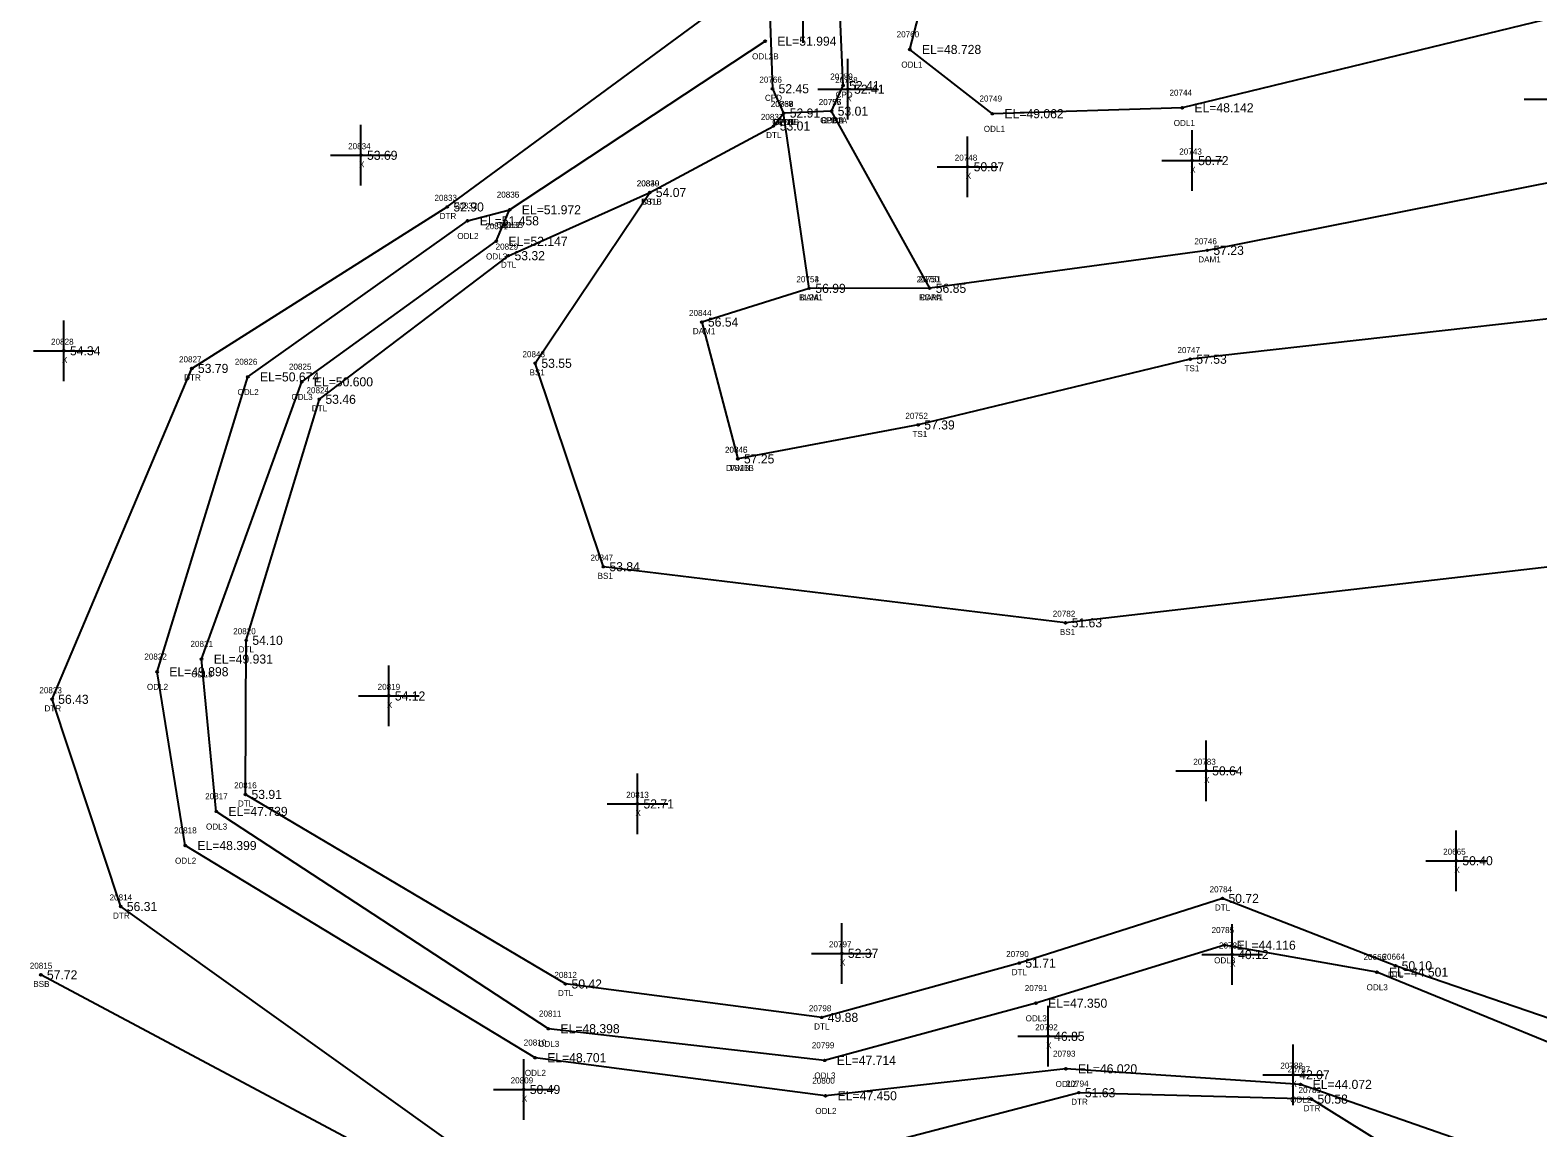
# Model space of a CAD drawing. Extents: x 2420351 to 2422725, y 845330 to 846558.
# Drawn here: x 2421386.7 to 2421635.3, y 845844 to 846025.1 of the extents above; entities that cross this region are included whole.
import ezdxf

# ---------------------------------------------------------------- set-up
doc = ezdxf.new("R2010")
doc.units = 0
for name, color, linetype in [('RD_DTM_BkLn1', 7, 'Continuous'), ('RD_DTM_BkLn2', 7, 'Continuous'), ('RD_DTM_BkLn_txCode', 7, 'Continuous'), ('RD_EX_Conc', 7, 'Continuous'), ('RD_EX_Conc_txCode', 7, 'Continuous'), ('RD_EX_Dam', 7, 'Continuous'), ('RD_EX_Dam_txCode', 7, 'Continuous'), ('RD_EX_DR_ErosCtrl', 7, 'Continuous'), ('RD_EX_DR_ErosCtrl_txCode', 7, 'Continuous'), ('RD_EX_H2O', 7, 'Continuous'), ('RD_EX_H2O_txCode', 7, 'Continuous'), ('RD_EX_Misc', 7, 'Continuous'), ('RD_EX_Misc_txCode', 7, 'Continuous'), ('RD_EX_TX_Conc_ELEV', 7, 'Continuous'), ('RD_EX_TX_Dam_ELEV', 7, 'Continuous'), ('RD_EX_TX_DR_ErosCtrl_ELEV', 7, 'Continuous'), ('RD_EX_TX_H2O_ELEV', 7, 'Continuous'), ('RD_EX_TX_Misc_ELEV', 7, 'Continuous'), ('RD_SMD_Locator', 7, 'Continuous')]:
    doc.layers.add(name, color=color, linetype=linetype)

msp = doc.modelspace()

# ---------------------------------------------------------------- linework, layer by layer
at = {"layer": 'RD_DTM_BkLn1'}
msp.add_line((2421515.21, 845982.5), (2421510.99, 846011.42), dxfattribs=at)
at = {"layer": 'RD_DTM_BkLn2'}
for points in [[(2421645.39, 845937.48), (2421557.48, 845927.33), (2421481.26, 845936.58), (2421470.04, 845970.14), (2421488.91, 845998.31)], [(2421645.39, 845937.48), (2421642.53, 845978.05), (2421578.04, 845970.81), (2421533.18, 845959.97), (2421503.44, 845954.37)], [(2421481.47, 845840.1), (2421460.78, 845830.74), (2421388.51, 845869.26)]]:
    msp.add_lwpolyline(points, dxfattribs=at)
at = {"layer": 'RD_EX_Conc'}
msp.add_line((2421518.9, 846011.73), (2421510.99, 846011.42), dxfattribs=at)
msp.add_lwpolyline([(2421518.9, 846011.73), (2421520.79, 846015.94), (2421519.59, 846043.78), (2421517.87, 846047.43), (2421509.82, 846047.43), (2421508.14, 846043.13), (2421509.15, 846015.43), (2421510.99, 846011.42)], dxfattribs=at)
at = {"layer": 'RD_EX_Dam'}
msp.add_lwpolyline([(2421642.53, 845978.05), (2421639.05, 846000.31), (2421580.85, 845988.77), (2421535.07, 845982.51), (2421515.21, 845982.5), (2421497.5, 845976.94), (2421503.44, 845954.37)], dxfattribs=at)
at = {"layer": 'RD_EX_DR_ErosCtrl'}
msp.add_line((2421535.07, 845982.51), (2421518.9, 846011.73), dxfattribs=at)
at = {"layer": 'RD_EX_H2O'}
for points in [[(2421769.97, 845784.59), (2421757.53, 845787.6), (2421742.96, 845811.73), (2421745.62, 845824.92), (2421731.55, 845840.59), (2421714.37, 845860.98), (2421703.55, 845865.16), (2421670.27, 845895.91), (2421653.18, 845938.84), (2421661.84, 845966.62), (2421645.65, 846012.9), (2421638.29, 846027.24), (2421576.72, 846012.28), (2421545.4, 846011.31), (2421531.8, 846021.91), (2421540.87, 846056.88), (2421568.83, 846092.43), (2421605.18, 846118.43)], [(2421712.23, 845851.64), (2421696.17, 845853.46), (2421673.72, 845844.59), (2421672.85, 845833.86), (2421657.19, 845821.05), (2421639.52, 845822.79), (2421628.75, 845828.72), (2421620.88, 845834.5), (2421598.01, 845848.76), (2421559.66, 845849.82), (2421519.66, 845839.33), (2421490.26, 845831.77), (2421489.16, 845834.56), (2421488.34, 845838.76), (2421481.47, 845840.1), (2421478.52, 845840.67), (2421462.88, 845836.78), (2421401.68, 845880.53), (2421390.37, 845914.71), (2421413.41, 845969.29), (2421455.53, 845995.93), (2421500.71, 846029.14), (2421506.65, 846045.11), (2421509.82, 846047.43)], [(2421708.19, 845857.7), (2421694.83, 845854.97), (2421672.77, 845845.6), (2421652.18, 845835.21), (2421629.45, 845839.56), (2421596.22, 845851.19), (2421557.52, 845853.76), (2421517.9, 845849.31), (2421470, 845855.59), (2421412.32, 845890.59), (2421407.69, 845919.26), (2421422.64, 845967.89), (2421458.88, 845993.64), (2421465.81, 845995.46), (2421507.94, 846023.27)], [(2421697.78, 845867.71), (2421684.61, 845864.63), (2421657.29, 845855.17), (2421611.89, 845870.76), (2421583.33, 845881.87), (2421549.84, 845871.2), (2421517.26, 845862.24), (2421475.01, 845867.75), (2421422.24, 845899.02), (2421422.38, 845924.44), (2421434.43, 845964.2), (2421465.61, 845987.89), (2421488.91, 845998.31), (2421509.34, 846009.28), (2421510.99, 846011.42)], [(2421703.55, 845865.16), (2421687.39, 845862.16), (2421656.9, 845850), (2421608.8, 845869.71), (2421583.67, 845874.15), (2421552.59, 845864.58), (2421517.75, 845855.15), (2421472.19, 845860.37), (2421417.44, 845896.22), (2421415.01, 845921.35), (2421431.52, 845967.08), (2421463.61, 845990.26), (2421465.81, 845995.46)]]:
    msp.add_lwpolyline(points, dxfattribs=at)
at = {"layer": 'RD_EX_Misc'}
for p, q in [((2421514.19, 846023.01), (2421514.19, 846033.01)), ((2421521.6, 846010.35), (2421521.6, 846020.35)), ((2421516.6, 846015.35), (2421526.6, 846015.35)), ((2421633.08, 846013.68), (2421643.08, 846013.68)), ((2421441.29, 845999.45), (2421441.29, 846009.45)), ((2421541.32, 845997.56), (2421541.32, 846007.56)), ((2421578.33, 845998.57), (2421578.33, 846008.57)), ((2421436.29, 846004.45), (2421446.29, 846004.45)), ((2421536.32, 846002.56), (2421546.32, 846002.56)), ((2421573.33, 846003.57), (2421583.33, 846003.57)), ((2421392.31, 845967.2), (2421392.31, 845977.2)), ((2421387.31, 845972.2), (2421397.31, 845972.2)), ((2421445.88, 845910.26), (2421445.88, 845920.26)), ((2421440.88, 845915.26), (2421450.88, 845915.26)), ((2421580.65, 845897.91), (2421580.65, 845907.91)), ((2421486.87, 845892.45), (2421486.87, 845902.45)), ((2421575.65, 845902.91), (2421585.65, 845902.91)), ((2421481.87, 845897.45), (2421491.87, 845897.45)), ((2421621.9, 845883.08), (2421621.9, 845893.08)), ((2421616.9, 845888.08), (2421626.9, 845888.08)), ((2421520.58, 845867.8), (2421520.58, 845877.8)), ((2421584.93, 845867.6), (2421584.93, 845877.6)), ((2421515.58, 845872.8), (2421525.58, 845872.8)), ((2421579.93, 845872.6), (2421589.93, 845872.6)), ((2421554.59, 845854.12), (2421554.59, 845864.12)), ((2421549.59, 845859.12), (2421559.59, 845859.12)), ((2421595.01, 845847.78), (2421595.01, 845857.78)), ((2421468.13, 845845.35), (2421468.13, 845855.35)), ((2421590.01, 845852.78), (2421600.01, 845852.78)), ((2421463.13, 845850.35), (2421473.13, 845850.35))]:
    msp.add_line(p, q, dxfattribs=at)
at = {"layer": 'RD_SMD_Locator'}
for centre in [(2421507.94, 846023.27), (2421531.8, 846021.91), (2421509.15, 846015.43), (2421520.79, 846015.94), (2421521.6, 846015.35), (2421510.99, 846011.42), (2421510.99, 846011.42), (2421510.99, 846011.42), (2421510.99, 846011.42), (2421518.9, 846011.73), (2421518.9, 846011.73), (2421518.9, 846011.73), (2421545.4, 846011.31), (2421576.72, 846012.28), (2421509.34, 846009.28), (2421441.29, 846004.45), (2421541.32, 846002.56), (2421578.33, 846003.57), (2421488.91, 845998.31), (2421488.91, 845998.31), (2421455.53, 845995.93), (2421465.81, 845995.46), (2421465.81, 845995.46), (2421458.88, 845993.64), (2421463.61, 845990.26), (2421465.61, 845987.89), (2421580.85, 845988.77), (2421515.21, 845982.5), (2421515.21, 845982.5), (2421535.07, 845982.51), (2421535.07, 845982.51), (2421497.5, 845976.94), (2421392.31, 845972.2), (2421413.41, 845969.29), (2421470.04, 845970.14), (2421578.04, 845970.81), (2421422.64, 845967.89), (2421431.52, 845967.08), (2421434.43, 845964.2), (2421533.18, 845959.97), (2421503.44, 845954.37), (2421503.44, 845954.37), (2421481.26, 845936.58), (2421557.48, 845927.33), (2421422.38, 845924.44), (2421407.69, 845919.26), (2421415.01, 845921.35), (2421390.37, 845914.71), (2421445.88, 845915.26), (2421580.65, 845902.91), (2421422.24, 845899.02), (2421486.87, 845897.45), (2421417.44, 845896.22), (2421412.32, 845890.59), (2421621.9, 845888.08), (2421401.68, 845880.53), (2421583.33, 845881.87), (2421520.58, 845872.8), (2421583.67, 845874.15), (2421584.93, 845872.6), (2421549.84, 845871.2), (2421608.8, 845869.71), (2421611.89, 845870.76), (2421388.51, 845869.26), (2421475.01, 845867.75), (2421552.59, 845864.58), (2421517.26, 845862.24), (2421472.19, 845860.37), (2421554.59, 845859.12), (2421470, 845855.59), (2421517.75, 845855.15), (2421557.52, 845853.76), (2421595.01, 845852.78), (2421468.13, 845850.35), (2421559.66, 845849.82), (2421596.22, 845851.19), (2421517.9, 845849.31), (2421598.01, 845848.76)]:
    msp.add_circle(centre, 0.15, dxfattribs=at)

# ---------------------------------------------------------------- texts
at = {"layer": 'RD_DTM_BkLn_txCode'}
for s, p in [('20769', (2421508.85, 846012.42)), ('BL2B', (2421509.32, 846009.42)), ('20849', (2421486.79, 845999.31)), ('BS1B', (2421487.49, 845996.31)), ('20754', (2421513.09, 845983.5)), ('BL2A', (2421513.52, 845980.5)), ('20848', (2421467.92, 845971.14)), ('20747', (2421575.92, 845971.81)), ('BS1', (2421469.09, 845968.14)), ('TS1', (2421577.08, 845968.81)), ('20752', (2421531.06, 845960.97)), ('TS1', (2421532.22, 845957.97)), ('20845', (2421501.32, 845955.37)), ('TS1B', (2421502.01, 845952.37)), ('20847', (2421479.14, 845937.58)), ('BS1', (2421480.31, 845934.58)), ('20782', (2421555.36, 845928.33)), ('BS1', (2421556.53, 845925.33)), ('20815', (2421386.68, 845870.26)), ('BSB', (2421387.26, 845867.26))]:
    msp.add_text(s, height=1, dxfattribs=at).set_placement(p)
at = {"layer": 'RD_EX_Conc_txCode'}
for s, p in [('20766', (2421506.98, 846016.43)), ('20759', (2421518.67, 846016.94)), ('CPD', (2421507.9, 846013.43)), ('CPD', (2421519.54, 846013.94)), ('20767', (2421508.85, 846012.42)), ('20768', (2421508.85, 846012.42)), ('20755', (2421516.78, 846012.73)), ('20757', (2421516.78, 846012.73)), ('CPD1B', (2421509.1, 846009.42)), ('CPDB', (2421509.27, 846009.42)), ('CPD1A', (2421517, 846009.73)), ('CPDA', (2421517.16, 846009.73))]:
    msp.add_text(s, height=1, dxfattribs=at).set_placement(p)
at = {"layer": 'RD_EX_Dam_txCode'}
for s, p in [('20746', (2421578.71, 845989.77)), ('DAM1', (2421579.35, 845986.77)), ('20753', (2421513.09, 845983.5)), ('20750', (2421532.91, 845983.51)), ('DAM1', (2421513.71, 845980.5)), ('DAM1', (2421533.57, 845980.51)), ('20844', (2421495.38, 845977.94)), ('DAM1', (2421496.01, 845974.94)), ('20846', (2421501.3, 845955.37)), ('DAM1B', (2421501.47, 845952.37))]:
    msp.add_text(s, height=1, dxfattribs=at).set_placement(p)
at = {"layer": 'RD_EX_DR_ErosCtrl_txCode'}
for s, p in [('20756', (2421516.76, 846012.73)), ('RDPB', (2421517.18, 846009.73)), ('20751', (2421533.23, 845983.51)), ('RDPA', (2421533.33, 845980.51))]:
    msp.add_text(s, height=1, dxfattribs=at).set_placement(p)
at = {"layer": 'RD_EX_H2O_txCode'}
for s, p in [('20760', (2421529.62, 846023.91)), ('ODL2B', (2421505.78, 846020.27)), ('ODL1', (2421530.39, 846018.91)), ('20749', (2421543.28, 846013.31)), ('20744', (2421574.61, 846014.28)), ('20838', (2421508.88, 846012.42)), ('20837', (2421507.23, 846010.28)), ('DTLB', (2421509.28, 846009.42)), ('ODL1', (2421543.99, 846008.31)), ('ODL1', (2421575.31, 846009.28)), ('DTL', (2421508.1, 846007.28)), ('20830', (2421486.75, 845999.31)), ('20833', (2421453.41, 845996.93)), ('20832', (2421456.76, 845995.64)), ('20836', (2421463.67, 845997.46)), ('20835', (2421463.69, 845997.46)), ('DTL', (2421487.66, 845996.31)), ('DTR', (2421454.26, 845993.93)), ('ODL2', (2421457.18, 845990.64)), ('20831', (2421461.78, 845992.26)), ('ODL3B', (2421463.65, 845992.46)), ('ODL2', (2421464.12, 845992.46)), ('20829', (2421463.49, 845988.89)), ('ODL3', (2421461.92, 845987.26)), ('DTL', (2421464.37, 845985.89)), ('20827', (2421411.29, 845970.29)), ('20826', (2421420.49, 845969.89)), ('20825', (2421429.41, 845969.08)), ('DTR', (2421412.14, 845967.29)), ('ODL2', (2421420.94, 845964.89)), ('ODL3', (2421429.83, 845964.08)), ('20824', (2421432.31, 845965.2)), ('DTL', (2421433.19, 845962.2)), ('20821', (2421413.18, 845923.35)), ('20820', (2421420.22, 845925.44)), ('20822', (2421405.57, 845921.26)), ('DTL', (2421421.13, 845922.44)), ('ODL3', (2421413.32, 845918.35)), ('ODL2', (2421406, 845916.26)), ('20823', (2421388.26, 845915.71)), ('DTR', (2421389.11, 845912.71)), ('20816', (2421420.38, 845900.02)), ('20817', (2421415.6, 845898.22)), ('DTL', (2421421, 845897.02)), ('20818', (2421410.49, 845892.59)), ('ODL3', (2421415.74, 845893.22)), ('ODL2', (2421410.63, 845887.59)), ('20814', (2421399.84, 845881.53)), ('20784', (2421581.22, 845882.87)), ('DTL', (2421582.09, 845879.87)), ('DTR', (2421400.41, 845878.53)), ('20785', (2421581.55, 845876.15)), ('20790', (2421547.68, 845872.2)), ('ODL3', (2421581.97, 845871.15)), ('20666', (2421606.61, 845871.71)), ('20664', (2421609.73, 845871.76)), ('20812', (2421473.18, 845868.75)), ('DTL', (2421548.6, 845869.2)), ('DTL', (2421610.65, 845868.76)), ('20791', (2421550.75, 845866.58)), ('ODL3', (2421607.11, 845866.71)), ('DTL', (2421473.77, 845865.75)), ('20811', (2421470.64, 845862.37)), ('20798', (2421515.14, 845863.24)), ('ODL3', (2421550.89, 845861.58)), ('DTL', (2421516.02, 845860.24)), ('20810', (2421468.13, 845857.59)), ('ODL3', (2421470.5, 845857.37)), ('20799', (2421515.63, 845857.15)), ('20793', (2421555.4, 845855.76)), ('ODL2', (2421468.31, 845852.59)), ('20800', (2421515.71, 845851.31)), ('ODL3', (2421516.05, 845852.15)), ('20787', (2421594.1, 845853.19)), ('ODL2', (2421555.83, 845850.76)), ('20794', (2421557.55, 845850.82)), ('20789', (2421595.89, 845849.76)), ('ODL2', (2421516.21, 845846.31)), ('DTR', (2421558.4, 845847.82)), ('ODL2', (2421594.52, 845848.19)), ('DTR', (2421596.74, 845846.76))]:
    msp.add_text(s, height=1, dxfattribs=at).set_placement(p)
at = {"layer": 'RD_EX_Misc_txCode'}
for s, p in [('20758', (2421519.48, 846016.35)), ('X', (2421521.29, 846013.35)), ('20834', (2421439.17, 846005.45)), ('20748', (2421539.2, 846003.56)), ('20743', (2421576.22, 846004.57)), ('X', (2421440.97, 846002.45)), ('X', (2421541.01, 846000.56)), ('X', (2421578.02, 846001.57)), ('20828', (2421390.19, 845973.2)), ('X', (2421391.99, 845970.2)), ('20819', (2421444.04, 845916.26)), ('X', (2421445.56, 845913.26)), ('20783', (2421578.53, 845903.91)), ('20813', (2421485.03, 845898.45)), ('X', (2421580.33, 845900.91)), ('X', (2421486.55, 845895.45)), ('20665', (2421619.73, 845889.08)), ('X', (2421621.58, 845886.08)), ('20797', (2421518.46, 845873.8)), ('20786', (2421582.78, 845873.6)), ('X', (2421520.26, 845870.8)), ('X', (2421584.61, 845870.6)), ('20792', (2421552.47, 845860.12)), ('X', (2421554.27, 845857.12)), ('20788', (2421592.89, 845853.78)), ('20809', (2421465.97, 845851.35)), ('X', (2421594.7, 845850.78)), ('X', (2421467.81, 845848.35))]:
    msp.add_text(s, height=1, dxfattribs=at).set_placement(p)
at = {"layer": 'RD_EX_TX_Conc_ELEV'}
for s, p in [('52.41', (2421521.79, 846015.19)), ('52.45', (2421510.15, 846014.68)), ('52.91', (2421511.99, 846010.67)), ('52.91', (2421511.99, 846010.67)), ('53.01', (2421519.9, 846010.98)), ('53.01', (2421519.9, 846010.98))]:
    msp.add_text(s, height=1.5, dxfattribs=at).set_placement(p)
at = {"layer": 'RD_EX_TX_Dam_ELEV'}
for s, p in [('57.23', (2421581.85, 845988.02)), ('56.99', (2421516.21, 845981.75)), ('56.85', (2421536.07, 845981.76)), ('56.54', (2421498.5, 845976.19)), ('57.25', (2421504.44, 845953.62))]:
    msp.add_text(s, height=1.5, dxfattribs=at).set_placement(p)
at = {"layer": 'RD_EX_TX_DR_ErosCtrl_ELEV'}
for s, p in [('53.01', (2421519.9, 846010.98)), ('56.85', (2421536.07, 845981.76))]:
    msp.add_text(s, height=1.5, dxfattribs=at).set_placement(p)
at = {"layer": 'RD_EX_TX_H2O_ELEV'}
for s, p in [('EL=51.994', (2421509.94, 846022.52)), ('EL=48.728', (2421533.8, 846021.16)), ('52.91', (2421511.99, 846010.67)), ('EL=49.062', (2421547.4, 846010.56)), ('EL=48.142', (2421578.72, 846011.53)), ('53.01', (2421510.34, 846008.53)), ('54.07', (2421489.91, 845997.56)), ('52.90', (2421456.53, 845995.18)), ('EL=51.458', (2421460.88, 845992.89)), ('EL=51.972', (2421467.81, 845994.71)), ('EL=51.972', (2421467.81, 845994.71)), ('EL=52.147', (2421465.61, 845989.51)), ('53.32', (2421466.61, 845987.14)), ('53.79', (2421414.41, 845968.54)), ('EL=50.674', (2421424.64, 845967.14)), ('EL=50.600', (2421433.52, 845966.33)), ('53.46', (2421435.43, 845963.45)), ('54.10', (2421423.38, 845923.69)), ('EL=49.931', (2421417.01, 845920.6)), ('EL=49.898', (2421409.69, 845918.51)), ('56.43', (2421391.37, 845913.96)), ('53.91', (2421423.24, 845898.27)), ('EL=47.739', (2421419.44, 845895.47)), ('EL=48.399', (2421414.32, 845889.84)), ('50.72', (2421584.33, 845881.12)), ('56.31', (2421402.68, 845879.78)), ('EL=44.116', (2421585.67, 845873.4)), ('51.71', (2421550.84, 845870.45)), ('EL=44.501', (2421610.8, 845868.96)), ('50.10', (2421612.89, 845870.01)), ('50.42', (2421476.01, 845867)), ('EL=47.350', (2421554.59, 845863.83)), ('49.88', (2421518.26, 845861.49)), ('EL=48.398', (2421474.19, 845859.62)), ('EL=48.701', (2421472, 845854.84)), ('EL=47.714', (2421519.75, 845854.4)), ('EL=46.020', (2421559.52, 845853.01)), ('EL=47.450', (2421519.9, 845848.56)), ('51.63', (2421560.66, 845849.07)), ('EL=44.072', (2421598.22, 845850.44)), ('50.58', (2421599.01, 845848.01))]:
    msp.add_text(s, height=1.5, dxfattribs=at).set_placement(p)
at = {"layer": 'RD_EX_TX_Misc_ELEV'}
for s, p in [('52.41', (2421522.6, 846014.6)), ('52.91', (2421511.99, 846010.67)), ('53.69', (2421442.29, 846003.7)), ('50.72', (2421579.33, 846002.82)), ('50.87', (2421542.32, 846001.81)), ('54.07', (2421489.91, 845997.56)), ('56.99', (2421516.21, 845981.75)), ('54.34', (2421393.31, 845971.45)), ('57.53', (2421579.04, 845970.06)), ('53.55', (2421471.04, 845969.39)), ('57.39', (2421534.18, 845959.22)), ('57.25', (2421504.44, 845953.62)), ('53.84', (2421482.26, 845935.83)), ('51.63', (2421558.48, 845926.58)), ('54.12', (2421446.88, 845914.51)), ('50.64', (2421581.65, 845902.16)), ('52.71', (2421487.87, 845896.7)), ('50.40', (2421622.9, 845887.33)), ('52.37', (2421521.58, 845872.05)), ('40.12', (2421585.93, 845871.85)), ('57.72', (2421389.51, 845868.51)), ('46.85', (2421555.59, 845858.37)), ('42.07', (2421596.01, 845852.03)), ('50.49', (2421469.13, 845849.6))]:
    msp.add_text(s, height=1.5, dxfattribs=at).set_placement(p)

doc.saveas('drawing.dxf')
